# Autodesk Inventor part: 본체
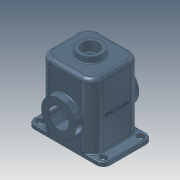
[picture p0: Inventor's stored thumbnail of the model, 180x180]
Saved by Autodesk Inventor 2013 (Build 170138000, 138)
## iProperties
Company: 한국ATC센터
Created: 2014-10
Part Number: 본체
Document SubType Name: Modeling
Designer: 한국ATC센터
Density: 1 g/cm^3
Material: 알루미늄 6061
Mass: 1088.52 g
Surface Area: 2150.09 cm^2
Volume: 1088.52 cm^3
Author: KYOUNG IL JANG
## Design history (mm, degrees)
sketch "스케치1"
  geometry: L1 (-70, 65)-(70, 65); L2 (70, 65)-(70, -65); L3 (70, -65)-(-70, -65); L4 (-70, -65)-(-70, 65); 3 further points
  constraints: 8 end point, 2 midpoint, 2 parallel, 1 horizontal, 1 horizontal alignment, 1 perpendicular, 1 vertical alignment
  dimensions: "d0" = 140 distance of L2.end L3.end; "d68" = 130 distance of L3.end L1.start
extrude "돌출1" new body sketch "스케치1" distance "d1" = 180; taper "d2" = 0 deg
fillet "모깎기1" dims "d3" = 20
feature "쉘1" dims "d4" = 10
sketch "스케치2"
  geometry: L1 (-70, 45)-(-70, -45) reference; L2 (-50, -65)-(-82, -65); L3 (-82, 65)-(-50, 65); L4 (-85, 57)-(-82, 57); L5 (-82, 41)-(-85, 41); L6 (-100, 47)-(-100, -47); A1 r 20 centre (-50, 45) between (-50, 65) and (-70, 45) reference; A2 r 20 centre (-50, -45) between (-70, -45) and (-50, -65) reference; A3 r 8 centre (-82, 49) between (-82, 41) and (-82, 57); A4 r 8 centre (-85, 49) between (-85, 57) and (-85, 41); A5 r 18 centre (-82, 47) between (-82, 65) and (-100, 47); A6 r 18 centre (-82, -47) between (-100, -47) and (-82, -65); 1 further point
  constraints: 10 end point, 9 tangent, 8 point on circle, 4 centre point, 2 parallel, 2 perpendicular, 1 equal radius
  dimensions: "d6" = 49 vertical distance of point (0, 0) A3.centre; "d8" = 16 distance between parallel lines of L4 L5; "d64" = 18 radius of A5; "d65" = 12 distance from line of A3.centre L1; "d66" = 30 distance between parallel lines of L6 L1; "d67" = 3 distance of A4.centre A3.centre
extrude "돌출2" join sketch "스케치2" distance "d9" = 10; taper "d10" = 0 deg
extrude "돌출3" cut sketch "스케치2" stored distance "d11" = 10; taper "d12" = 0 deg
sketch "스케치3"
  geometry: L1 (-65, 0)-(-65, 180) reference; L2 (-55, 0)-(-55, 170) reference; L3 (-83, 75)-(-51, 75); L4 (45, 0)-(-45, 0) reference; L5 (-83, 75)-(-83, 120.5); L6 (-83, 120.5)-(-55, 120.5); L7 (-55, 120.5)-(-51, 116.5); L8 (-51, 116.5)-(-51, 75); 2 further points
  constraints: 10 end point, 4 perpendicular, 1 point on line
  dimensions: "d13" = 75 distance between parallel lines of L3 L4; "d14" = 18 distance from line of L1 L3.start; "d15" = 4 distance from line of L3.end L2; "d16" = 91 diameter of L6 L3; "d17" = 135 deg angle of L7 L2
revolve "회전1" sketch "스케치3" stored, may be unused: angle "d18" = 90 deg
sketch "스케치4"
  geometry: C1 r 45.5 at (0, 0) reference; 2 further points
  constraints: 1 vertical alignment
  dimensions: "d19" = 35 distance of C1.centre point (0, 35)
hole "구멍1" sketch "스케치4" at (0, 35) diameter "d20" = 3.459; stored, may be unused: countersink angle "d24" = 90 deg, drill point angle "d26" = 118 deg; dims "d21" = 13, "d22" = 4, "d23" = 2, "d25" = 16
fillet "모깎기2" dims "d30" = 3
hole "구멍2" diameter "d33" = 52; stored, may be unused: countersink angle "d37" = 90 deg, drill point angle "d39" = 118 deg; dims "d31" = 10, "d32" = 10, "d34" = 13, "d35" = 4, "d36" = 2, "d38" = 16
sketch "스케치5"
  geometry: C1 r 31 at (0, 0); 1 further point
  constraints: 1 centre point, 1 coincident
  dimensions: "d40" = 62 diameter of C1
extrude "돌출4" join sketch "스케치5" distance "d41" = 15; taper "d42" = 0 deg
hole "구멍3" diameter "d45" = 43; stored, may be unused: countersink angle "d49" = 90 deg, drill point angle "d51" = 118 deg; dims "d43" = 10, "d44" = 10, "d46" = 13, "d47" = 4, "d48" = 2, "d50" = 16
fillet "모깎기3" dims "d52" = 3
fillet "모깎기4" dims "d53" = 3
chamfer "모따기1" distance "d55" = 1; stored, may be unused: second distance "d56" = 2, angle "d57" = 45 deg
sketch "스케치6"
  geometry: 2 further points
  constraints: 1 vertical alignment, 1 other
  dimensions: "d71" = 90 distance of point (0, 0) point (0, 90)
feature "엠보싱2" sketch "스케치6" dims "d0" = 140, "d68" = 130, "d72" = 1, "d73" = 0
fillet "모깎기6" dims "d74" = 10
sketch "스케치7"
  geometry: C1 r 15 at (0, 0); C2 r 21.5 at (0, 0) reference; C3 r 25 at (0, 0); 1 further point
  constraints: 2 centre point, 2 coincident
  dimensions: "d61" = 30 diameter of C1; "d75" = 50 diameter of C3
extrude "돌출5" join sketch "스케치7" distance "d62" = 10; taper "d63" = 0 deg
feature "면 이동1" dims "d76" = 1
fillet "모깎기7" dims "d77" = 3
node "솔리드1"
mirror "대칭1"
mirror "대칭2"
pattern_circular "원형 패턴1" dims angle "d28" = 360 deg
mirror "대칭3"
